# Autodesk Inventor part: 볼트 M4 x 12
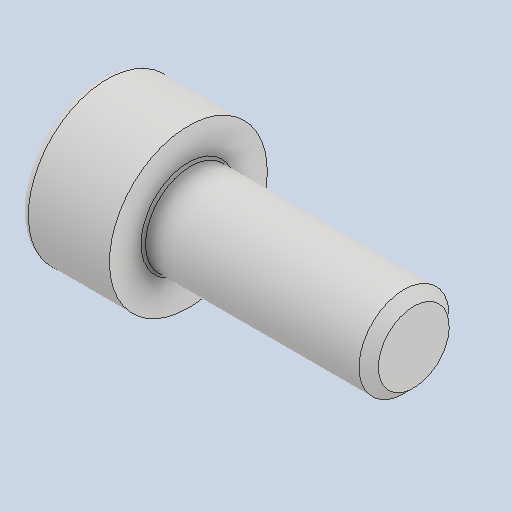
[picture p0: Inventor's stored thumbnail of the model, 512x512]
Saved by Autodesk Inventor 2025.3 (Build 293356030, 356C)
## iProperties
Created: 2025-08
Part Number: 볼트 M4 x 12
Material: 스테인리스강
Description: 6각머리 태핑 나사
Document SubType Name: Modeling
Designer: user
Density: 8.08 g/cm^3
Appearance: 기본값
Author: jhkim
Sending System: Autodesk Inventor 2026
Preprocessor: ST-DEVELOPER v20.1
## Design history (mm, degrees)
sketch "스케치1"
  geometry: 1 further point
  constraints: 1 other
feature "Solid1"
node "솔리드1"
